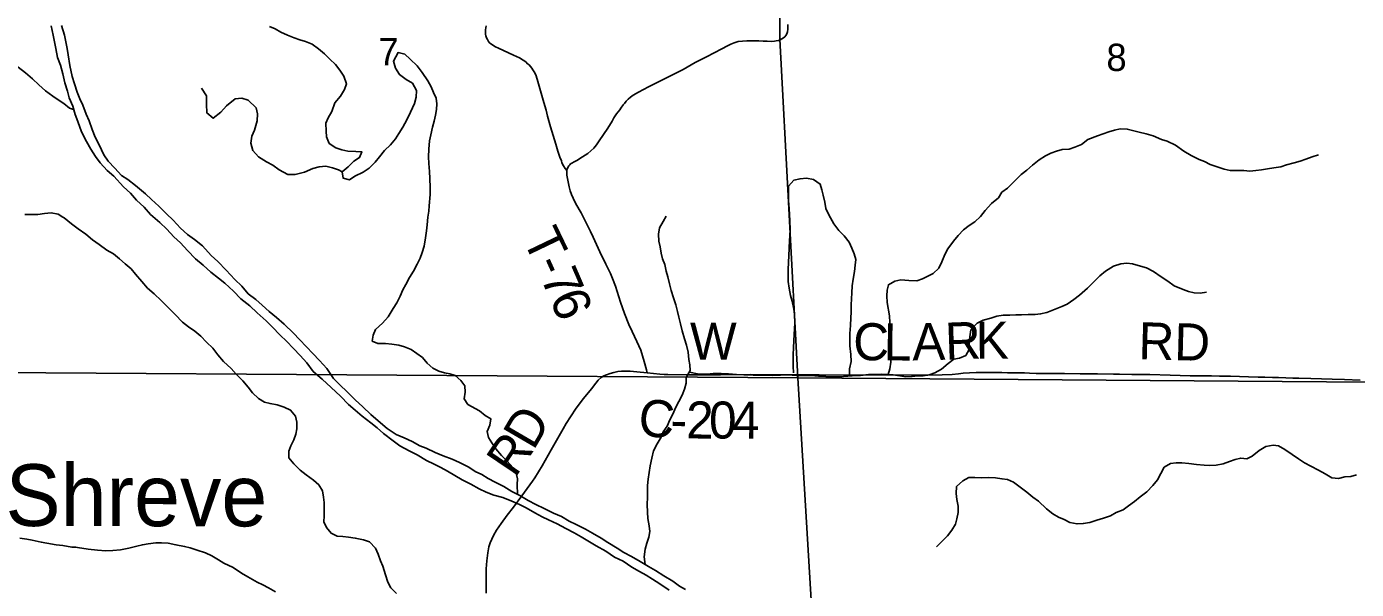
# Model space of a CAD drawing. Extents: x 1985906 to 2360102, y 891258 to 1222054.
# Drawn here: x 2108716 to 2119481, y 981202 to 985761 of the extents above; entities that cross this region are included whole.
import ezdxf

# ---------------------------------------------------------------- set-up
doc = ezdxf.new("R2010")
doc.units = 0
for name, color, linetype in [('GM_X_County_Road', 7, 'Continuous'), ('GM_X_County_Road_Text', 7, 'Continuous'), ('GM_X_Major_River', 7, 'Continuous'), ('GM_X_Minor_River', 7, 'Continuous'), ('GM_X_Minor_River_Text', 7, 'Continuous'), ('GM_X_Section', 7, 'Continuous'), ('GM_X_Section_Text', 7, 'Continuous'), ('GM_X_Township_Road', 7, 'Continuous'), ('GM_X_Township_Road_Text', 7, 'Continuous')]:
    doc.layers.add(name, color=color, linetype=linetype)

msp = doc.modelspace()

# ---------------------------------------------------------------- linework, layer by layer
at = {"layer": 'GM_X_County_Road'}
for points in [[(2112436, 981171), (2112435, 981319), (2112436, 981368), (2112441, 981434), (2112449, 981499), (2112459, 981548), (2112468, 981579), (2112481, 981610), (2112496, 981640), (2112521, 981682), (2112558, 981737), (2112607, 981803), (2112657, 981867), (2112726, 981959), (2112812, 982078), (2112831, 982105), (2112889, 982204), (2112962, 982332), (2113060, 982502), (2113085, 982545), (2113119, 982601), (2113165, 982669), (2113225, 982749), (2113289, 982827), (2113323, 982873), (2113344, 982898), (2113367, 982918), (2113390, 982932), (2113409, 982940), (2113440, 982950), (2113469, 982958), (2113501, 982966), (2113532, 982970), (2113562, 982971), (2113603, 982970), (2113655, 982965), (2113739, 982957)], [(2113739, 982957), (2113791, 982951), (2113842, 982945), (2113878, 982942), (2113907, 982942), (2114071, 982940), (2114332, 982941), (2114578, 982943), (2115117, 982940), (2115133, 982940), (2115880, 982938), (2116012, 982938), (2116127, 982940), (2116209, 982944), (2116260, 982949), (2116297, 982953), (2116349, 982955), (2116404, 982958), (2116448, 982959), (2116491, 982960), (2116541, 982960), (2116610, 982959), (2116656, 982957), (2116719, 982957), (2116793, 982955), (2116835, 982954), (2116889, 982952), (2116944, 982952), (2117021, 982952), (2117117, 982952), (2117245, 982949), (2117384, 982947), (2117515, 982945), (2117564, 982945), (2117662, 982944), (2117710, 982944), (2117760, 982944), (2117809, 982943), (2117973, 982937), (2118136, 982933), (2118218, 982932), (2118267, 982932), (2118307, 982931), (2118374, 982929), (2118462, 982929), (2118608, 982925), (2118686, 982922), (2118739, 982920), (2118801, 982919), (2118851, 982918), (2118909, 982916), (2118967, 982914), (2119015, 982912), (2119111, 982911), (2119285, 982906), (2119385, 982903), (2119511, 982898)]]:
    msp.add_lwpolyline(points, dxfattribs=at)
at = {"layer": 'GM_X_Major_River'}
for points in [[(2108914, 985766), (2108930, 985690), (2108942, 985636), (2108953, 985584), (2108967, 985511), (2108991, 985449), (2109009, 985379), (2109026, 985305), (2109046, 985237), (2109060, 985183), (2109089, 985115), (2109109, 985049), (2109131, 984991), (2109161, 984909), (2109202, 984829), (2109236, 984767), (2109274, 984709), (2109312, 984657), (2109369, 984596), (2109421, 984550), (2109501, 984462), (2109557, 984412), (2109606, 984356), (2109668, 984298), (2109720, 984239), (2109794, 984175), (2109850, 984121), (2109909, 984059), (2109961, 984009), (2110019, 983947), (2110083, 983880), (2110145, 983828), (2110206, 983772), (2110270, 983724), (2110320, 983682), (2110390, 983619), (2110450, 983557), (2110522, 983499), (2110581, 983443), (2110655, 983377)], [(2111437, 982680), (2111375, 982737), (2111313, 982799), (2111250, 982863), (2111200, 982911), (2111146, 982991), (2111086, 983057), (2111032, 983113), (2110981, 983166), (2110925, 983226), (2110877, 983278), (2110801, 983350), (2110739, 983404), (2110680, 983454), (2110622, 983505), (2110572, 983551), (2110510, 983597), (2110458, 983657), (2110402, 983713), (2110331, 983787), (2110265, 983858), (2110211, 983908), (2110139, 983984), (2110076, 984036), (2110018, 984076), (2109962, 984127), (2109902, 984193), (2109848, 984245), (2109786, 984307), (2109727, 984361), (2109677, 984405), (2109597, 984474), (2109535, 984522), (2109483, 984556), (2109429, 984614), (2109376, 984670), (2109340, 984722), (2109304, 984802), (2109272, 984864), (2109247, 984926), (2109221, 984998), (2109197, 985052), (2109170, 985124), (2109146, 985176), (2109126, 985230), (2109104, 985296), (2109085, 985356), (2109065, 985446), (2109053, 985532), (2109044, 985582), (2109034, 985636), (2109022, 985690), (2108998, 985770)], [(2110655, 983377), (2110705, 983329), (2110769, 983262), (2110819, 983212), (2110876, 983154), (2110930, 983098), (2110984, 983038), (2111036, 982966), (2111108, 982905), (2111181, 982837), (2111257, 982767), (2111323, 982701), (2111375, 982653), (2111433, 982605), (2111502, 982550), (2111554, 982510), (2111606, 982464), (2111682, 982406), (2111738, 982366), (2111814, 982325), (2111878, 982291), (2111952, 982247), (2112015, 982217), (2112069, 982190), (2112123, 982160), (2112183, 982124), (2112243, 982090), (2112311, 982055), (2112379, 982017), (2112435, 981989), (2112497, 981965), (2112571, 981946), (2112645, 981916), (2112705, 981890), (2112759, 981864), (2112831, 981821), (2112889, 981791), (2112941, 981765), (2113010, 981733), (2113082, 981696), (2113148, 981660), (2113204, 981628), (2113258, 981596), (2113326, 981556), (2113404, 981513), (2113476, 981463), (2113544, 981431), (2113616, 981383), (2113678, 981346), (2113731, 981318), (2113783, 981286), (2113841, 981246), (2113917, 981196)], [(2114051, 981201), (2114001, 981227), (2113946, 981269), (2113874, 981313), (2113808, 981354), (2113750, 981388), (2113684, 981428), (2113612, 981468), (2113550, 981501), (2113496, 981535), (2113422, 981583), (2113366, 981617), (2113297, 981658), (2113241, 981690), (2113165, 981728), (2113109, 981756), (2113045, 981792), (2112981, 981819), (2112905, 981857), (2112837, 981889), (2112775, 981922), (2112709, 981962), (2112645, 981996), (2112579, 982036), (2112509, 982072), (2112453, 982101), (2112400, 982133), (2112348, 982157), (2112296, 982191), (2112220, 982230), (2112162, 982256), (2112088, 982284), (2112022, 982310), (2111950, 982345), (2111900, 982365), (2111836, 982399), (2111772, 982429), (2111708, 982456), (2111636, 982506), (2111582, 982552), (2111503, 982620), (2111437, 982680)]]:
    msp.add_lwpolyline(points, dxfattribs=at)
at = {"layer": 'GM_X_Minor_River'}
for points in [[(2110681, 985762), (2110729, 985742), (2110773, 985716), (2110827, 985692), (2110883, 985670), (2110929, 985654), (2110973, 985640), (2111027, 985619), (2111079, 985581), (2111127, 985541), (2111171, 985497), (2111217, 985453), (2111251, 985408), (2111285, 985358), (2111305, 985296), (2111289, 985252), (2111256, 985196), (2111210, 985142), (2111186, 985073), (2111156, 985023), (2111138, 984979), (2111140, 984915), (2111144, 984867), (2111164, 984815), (2111220, 984780), (2111268, 984762), (2111316, 984752), (2111380, 984750), (2111430, 984746), (2111412, 984700), (2111364, 984670), (2111318, 984624), (2111270, 984584), (2111278, 984534), (2111330, 984519), (2111374, 984549), (2111440, 984581), (2111490, 984613), (2111538, 984662), (2111574, 984706), (2111614, 984756), (2111662, 984802), (2111702, 984852), (2111730, 984896), (2111762, 984946), (2111794, 985006), (2111824, 985068), (2111855, 985137), (2111869, 985189), (2111873, 985243), (2111839, 985303)], [(2109096, 985090), (2109062, 985099), (2109016, 985139), (2108972, 985167), (2108928, 985197), (2108868, 985240), (2108816, 985290), (2108764, 985338), (2108708, 985386), (2108648, 985431), (2108602, 985463), (2108540, 985501), (2108488, 985531), (2108446, 985542)], [(2111839, 985303), (2111789, 985331), (2111735, 985372), (2111703, 985424), (2111685, 985482), (2111723, 985550), (2111777, 985538), (2111821, 985498), (2111877, 985444), (2111919, 985389), (2111963, 985321), (2111991, 985273), (2112011, 985227), (2112031, 985182), (2112037, 985134), (2112033, 985088), (2112027, 985044), (2112016, 984994), (2112002, 984946), (2111988, 984884), (2111978, 984835), (2111972, 984769), (2111970, 984705), (2111972, 984651), (2111978, 984587), (2111980, 984530), (2111982, 984458), (2111982, 984402), (2111975, 984310), (2111971, 984266), (2111965, 984217), (2111959, 984155), (2111953, 984107), (2111945, 984049), (2111933, 983983), (2111919, 983931), (2111901, 983884), (2111877, 983836), (2111847, 983780), (2111815, 983728), (2111786, 983672), (2111762, 983628), (2111740, 983578), (2111712, 983522), (2111684, 983477), (2111642, 983409), (2111598, 983359), (2111540, 983307), (2111522, 983261), (2111514, 983213), (2111560, 983195), (2111620, 983193), (2111672, 983189), (2111728, 983180), (2111774, 983166), (2111828, 983144), (2111874, 983114), (2111920, 983080), (2111958, 983034), (2112004, 982995), (2112052, 982971), (2112098, 982957), (2112142, 982947), (2112186, 982935), (2112230, 982895), (2112264, 982851), (2112267, 982800), (2112259, 982746), (2112287, 982700), (2112383, 982648), (2112427, 982611), (2112473, 982585), (2112465, 982533), (2112445, 982481), (2112455, 982433), (2112483, 982389), (2112515, 982342), (2112561, 982288), (2112605, 982240), (2112653, 982190), (2112679, 982144), (2112691, 982099), (2112687, 982053), (2112691, 981972)], [(2111270, 984584), (2111242, 984600), (2111192, 984618), (2111138, 984630), (2111084, 984626), (2111032, 984612), (2110965, 984581), (2110891, 984563), (2110831, 984564), (2110761, 984600), (2110709, 984638), (2110657, 984666), (2110593, 984706), (2110548, 984757), (2110532, 984816), (2110538, 984872), (2110562, 984922), (2110583, 984998), (2110585, 985054), (2110573, 985104), (2110510, 985166), (2110457, 985180), (2110405, 985176), (2110333, 985119), (2110287, 985067), (2110226, 985018), (2110175, 985062), (2110171, 985132), (2110173, 985201), (2110133, 985262)], [(2115691, 982943), (2115703, 982989), (2115711, 983042), (2115709, 983090), (2115703, 983138), (2115699, 983194), (2115699, 983246), (2115703, 983363), (2115700, 983417), (2115682, 983525), (2115680, 983579), (2115682, 983626), (2115692, 983670), (2115744, 983700), (2115794, 983710), (2115858, 983704), (2115922, 983701), (2115968, 983719), (2116012, 983739), (2116056, 983761), (2116100, 983803), (2116126, 983856), (2116150, 983916), (2116174, 983960), (2116219, 984022), (2116257, 984070), (2116301, 984114), (2116345, 984150), (2116391, 984180), (2116439, 984222), (2116477, 984272), (2116527, 984328), (2116585, 984375), (2116611, 984419), (2116657, 984451), (2116768, 984563), (2116812, 984599), (2116858, 984639), (2116914, 984681), (2116964, 984713), (2117008, 984735), (2117052, 984753), (2117100, 984765), (2117156, 984767), (2117202, 984783), (2117256, 984805), (2117306, 984847), (2117384, 984875), (2117432, 984891), (2117478, 984909), (2117524, 984923), (2117570, 984933), (2117626, 984931), (2117678, 984917), (2117722, 984906), (2117780, 984892), (2117836, 984876), (2117902, 984846), (2117948, 984832), (2118016, 984800), (2118084, 984753), (2118144, 984717), (2118208, 984685), (2118252, 984667), (2118298, 984645), (2118410, 984606), (2118460, 984596), (2118522, 984596), (2118570, 984594), (2118618, 984590), (2118666, 984594), (2118714, 984600), (2118762, 984608), (2118812, 984616), (2118870, 984626), (2118914, 984640), (2118976, 984656), (2119027, 984672), (2119071, 984686), (2119123, 984706), (2119175, 984721)], [(2115378, 982930), (2115377, 982988), (2115391, 983048), (2115387, 983106), (2115379, 983175), (2115381, 983223), (2115381, 983275), (2115385, 983341), (2115389, 983401), (2115391, 983447), (2115392, 983506), (2115394, 983556), (2115396, 983604), (2115398, 983662), (2115406, 983714), (2115418, 983776), (2115424, 983829), (2115428, 983875), (2115414, 983919), (2115396, 983965), (2115374, 984015), (2115334, 984066), (2115290, 984110), (2115250, 984164), (2115209, 984236), (2115187, 984288), (2115177, 984339), (2115165, 984395), (2115153, 984439), (2115139, 984485), (2115087, 984521), (2115029, 984534), (2114977, 984528), (2114927, 984518), (2114885, 984468), (2114885, 984349), (2114889, 984287), (2114894, 984187), (2114898, 984116), (2114894, 984070), (2114892, 984026), (2114888, 983968), (2114886, 983902), (2114884, 983856), (2114880, 983789), (2114880, 983743), (2114882, 983697), (2114890, 983643), (2114901, 983583), (2114913, 983536), (2114927, 983472), (2114933, 983428), (2114935, 983360), (2114931, 983312), (2114927, 983219), (2114923, 983157), (2114921, 983107), (2114921, 983057), (2114921, 983011), (2114923, 982957)], [(2109010, 984218), (2108970, 984242), (2108916, 984252), (2108860, 984246), (2108808, 984239), (2108702, 984239)], [(2109468, 983880), (2109418, 983919), (2109366, 983951), (2109302, 983997), (2109250, 984033), (2109194, 984079), (2109132, 984122), (2109078, 984162), (2109020, 984212), (2109010, 984218)], [(2113723, 981405), (2113714, 981466), (2113724, 981528), (2113736, 981576), (2113754, 981624), (2113760, 981670), (2113756, 981716), (2113745, 981777), (2113741, 981827), (2113739, 981889), (2113741, 981949), (2113741, 981995), (2113743, 982044), (2113747, 982094), (2113755, 982148), (2113763, 982204), (2113777, 982266), (2113791, 982324), (2113821, 982382), (2113853, 982435), (2113870, 982479), (2113902, 982523), (2113924, 982575), (2113946, 982621), (2113972, 982677), (2113996, 982723), (2114022, 982775), (2114042, 982824), (2114056, 982872), (2114056, 982918), (2114088, 982974), (2114084, 983020), (2114076, 983064), (2114071, 983125), (2114059, 983181), (2114043, 983231), (2114023, 983297), (2114009, 983353), (2113997, 983408), (2113985, 983452), (2113971, 983508), (2113953, 983564), (2113935, 983622), (2113919, 983677), (2113907, 983733), (2113893, 983779), (2113883, 983833), (2113864, 983881), (2113854, 983925), (2113844, 983978), (2113834, 984022), (2113830, 984080), (2113840, 984130), (2113868, 984182), (2113894, 984226)], [(2111709, 981168), (2111665, 981216), (2111641, 981260), (2111621, 981321), (2111599, 981389), (2111581, 981433), (2111561, 981487), (2111541, 981537), (2111491, 981588), (2111443, 981604), (2111377, 981618), (2111323, 981626), (2111275, 981630), (2111229, 981634), (2111181, 981658), (2111143, 981703), (2111122, 981749), (2111124, 981797), (2111124, 981905), (2111120, 981949), (2111110, 982000), (2111082, 982048), (2111038, 982088), (2110980, 982130), (2110930, 982168), (2110880, 982219), (2110840, 982267), (2110840, 982321), (2110856, 982365), (2110878, 982413), (2110894, 982459), (2110903, 982504), (2110903, 982558), (2110893, 982604), (2110853, 982654), (2110801, 982678), (2110743, 982698), (2110687, 982707), (2110643, 982719), (2110593, 982749), (2110545, 982795), (2110509, 982839), (2110467, 982892), (2110413, 982946), (2110373, 982992), (2110311, 983048), (2110263, 983103), (2110223, 983157), (2110171, 983205), (2110127, 983253), (2110079, 983293), (2110027, 983328), (2109979, 983368), (2109919, 983430), (2109858, 983488), (2109804, 983541), (2109748, 983595), (2109694, 983643), (2109650, 983695), (2109598, 983756), (2109562, 983800), (2109514, 983840), (2109468, 983880)], [(2114081, 982963), (2114160, 982946), (2114224, 982946), (2114274, 982950), (2114338, 982952), (2114398, 982949), (2114462, 982943), (2114522, 982941), (2114598, 982937), (2114689, 982937), (2114753, 982935), (2114819, 982937), (2114881, 982939), (2114945, 982936), (2115007, 982936), (2115067, 982934), (2115127, 982930), (2115185, 982926), (2115253, 982924), (2115329, 982926), (2115399, 982932), (2115467, 982936), (2115531, 982942), (2115585, 982943), (2115635, 982945), (2115731, 982941), (2115785, 982931), (2115833, 982923), (2115885, 982927), (2115929, 982931), (2115975, 982933), (2116023, 982941), (2116069, 982957), (2116123, 982985), (2116175, 983033), (2116223, 983067), (2116269, 983075), (2116319, 983097), (2116347, 983145), (2116347, 983199), (2116352, 983249), (2116360, 983305), (2116410, 983358), (2116460, 983382), (2116522, 983399), (2116570, 983415), (2116622, 983423), (2116676, 983423), (2116724, 983425), (2116770, 983425), (2116824, 983429), (2116880, 983429), (2116924, 983433), (2116976, 983445), (2117096, 983493), (2117140, 983513), (2117194, 983549), (2117240, 983585), (2117304, 983641), (2117351, 983687), (2117403, 983741), (2117451, 983779), (2117515, 983819), (2117575, 983839), (2117623, 983845), (2117669, 983839), (2117733, 983821), (2117781, 983807), (2117839, 983777), (2117901, 983734), (2117955, 983700), (2118007, 983662), (2118079, 983630), (2118123, 983616), (2118169, 983603), (2118215, 983601), (2118267, 983611)], [(2116081, 981546), (2116121, 981588), (2116171, 981636), (2116207, 981682), (2116235, 981730), (2116247, 981775), (2116256, 981825), (2116256, 981875), (2116246, 981929), (2116240, 981979), (2116244, 982035), (2116296, 982082), (2116344, 982108), (2116392, 982109), (2116450, 982105), (2116504, 982109), (2116560, 982105), (2116612, 982099), (2116656, 982091), (2116704, 982071), (2116760, 982031), (2116812, 981990), (2116862, 981950), (2116908, 981916), (2116972, 981856), (2117024, 981814), (2117070, 981787), (2117114, 981767), (2117160, 981745), (2117220, 981733), (2117270, 981735), (2117322, 981745), (2117380, 981763), (2117434, 981779), (2117490, 981797), (2117536, 981825), (2117592, 981847), (2117636, 981879), (2117684, 981915), (2117730, 981953), (2117784, 981993), (2117832, 982045), (2117870, 982089), (2117899, 982141), (2117925, 982191), (2117977, 982223), (2118021, 982227), (2118067, 982227), (2118125, 982223), (2118187, 982213), (2118249, 982209), (2118295, 982207), (2118347, 982209), (2118403, 982219), (2118453, 982237), (2118501, 982255), (2118545, 982266), (2118593, 982260), (2118637, 982280), (2118695, 982328), (2118747, 982360), (2118807, 982370), (2118851, 982364), (2118901, 982334), (2118961, 982296), (2119013, 982260), (2119061, 982226), (2119111, 982199), (2119173, 982169), (2119227, 982137), (2119283, 982107), (2119335, 982101), (2119387, 982113), (2119435, 982117), (2119483, 982129)], [(2109114, 981543), (2109083, 981545), (2109009, 981558), (2108956, 981562), (2108880, 981576), (2108834, 981586), (2108762, 981600), (2108718, 981608), (2108660, 981616)], [(2110731, 981182), (2110675, 981214), (2110627, 981238), (2110583, 981262), (2110507, 981304), (2110455, 981334), (2110389, 981379), (2110313, 981415), (2110269, 981441), (2110215, 981473), (2110165, 981499), (2110097, 981520), (2110039, 981540), (2109995, 981550), (2109925, 981564), (2109861, 981576), (2109807, 981578), (2109761, 981580), (2109701, 981572), (2109653, 981564), (2109609, 981553), (2109543, 981537), (2109477, 981523), (2109415, 981517), (2109357, 981515), (2109289, 981521), (2109213, 981527), (2109129, 981541), (2109114, 981543)]]:
    msp.add_lwpolyline(points, dxfattribs=at)
at = {"layer": 'GM_X_Section'}
for points in [[(2114822, 988281), (2114814, 985660), (2114959, 982915), (2108465, 982960), (2108488, 988311)], [(2120191, 988188), (2120308, 982876), (2114959, 982915), (2114814, 985660), (2114822, 988281)], [(2114959, 982915), (2115107, 980441), (2115159, 977489), (2108525, 977560), (2108465, 982960)], [(2120308, 982876), (2120424, 977532), (2115159, 977489), (2115107, 980441), (2114959, 982915)]]:
    msp.add_lwpolyline(points, close=True, dxfattribs=at)
at = {"layer": 'GM_X_Township_Road'}
for points in [[(2113089, 984595), (2113076, 984612), (2113063, 984632), (2113050, 984658), (2113045, 984673), (2113033, 984703), (2113017, 984753), (2113000, 984809), (2112957, 984948), (2112933, 985036), (2112921, 985084), (2112904, 985147), (2112848, 985334), (2112837, 985369), (2112824, 985395), (2112815, 985410), (2112805, 985425), (2112794, 985438), (2112784, 985450), (2112772, 985460), (2112757, 985474), (2112735, 985489), (2112705, 985507), (2112658, 985528), (2112535, 985585), (2112511, 985598), (2112482, 985616), (2112464, 985629), (2112454, 985641), (2112446, 985655), (2112440, 985669), (2112434, 985685), (2112430, 985700), (2112430, 985716), (2112430, 985734), (2112435, 985766)], [(2113089, 984595), (2113091, 984607), (2113096, 984619), (2113105, 984633), (2113114, 984642), (2113120, 984648), (2113130, 984655), (2113148, 984665), (2113169, 984677), (2113217, 984707), (2113258, 984734), (2113284, 984755), (2113307, 984777), (2113329, 984802), (2113352, 984835), (2113387, 984887), (2113420, 984938), (2113455, 984994), (2113471, 985022), (2113492, 985054), (2113517, 985087), (2113526, 985101), (2113545, 985127), (2113556, 985139), (2113569, 985156), (2113585, 985173), (2113604, 985189), (2113626, 985205), (2113669, 985230), (2113749, 985273), (2113865, 985330), (2113944, 985370), (2114030, 985414), (2114129, 985469), (2114221, 985516), (2114345, 985580), (2114389, 985605), (2114417, 985619), (2114444, 985630), (2114476, 985639), (2114511, 985644), (2114546, 985646), (2114593, 985646), (2114644, 985645), (2114678, 985644), (2114711, 985643), (2114744, 985641), (2114770, 985643), (2114785, 985646), (2114803, 985649), (2114817, 985654), (2114831, 985662), (2114843, 985669), (2114853, 985678), (2114863, 985688), (2114871, 985703), (2114875, 985717), (2114877, 985739), (2114877, 985777)], [(2113739, 982957), (2113734, 982980), (2113715, 983049), (2113687, 983139), (2113655, 983210), (2113619, 983292), (2113591, 983349), (2113556, 983438), (2113523, 983528), (2113483, 983658), (2113459, 983721), (2113442, 983762), (2113405, 983837), (2113357, 983936), (2113344, 983966), (2113303, 984054), (2113280, 984101), (2113242, 984178), (2113204, 984252), (2113163, 984326), (2113140, 984370), (2113127, 984400), (2113117, 984431), (2113108, 984462), (2113089, 984558), (2113088, 984575), (2113088, 984591), (2113089, 984595)]]:
    msp.add_lwpolyline(points, dxfattribs=at)

# ---------------------------------------------------------------- texts
at = {"layer": 'GM_X_County_Road_Text'}
for s, rotation, p in [('W', 0, (2114086, 983063)), ('C', 359.5824, (2115407, 983059)), ('L', 359.6913, (2115654, 983057)), ('A', 1.3032, (2115888, 983056)), ('R', 2.0668, (2116156, 983062)), ('K', 0.2532, (2116400, 983071)), ('RD', 358.5218, (2117714, 983067)), ('D', 59.7292, (2112819, 982321)), ('C', 355.3934, (2113661, 982448)), ('2', 359.6347, (2114054, 982425)), ('0', 359.9159, (2114240, 982424)), ('4', 359.9957, (2114426, 982424)), ('-', 359.0334, (2113927, 982427)), ('R', 56.016, (2112670, 982099))]:
    msp.add_text(s, height=300, rotation=rotation, dxfattribs=at).set_placement(p)
at = {"layer": 'GM_X_Minor_River_Text'}
msp.add_text('Shreve', height=500.1, rotation=359.9084, dxfattribs=at).set_placement((2108545, 981716))
at = {"layer": 'GM_X_Section_Text'}
for s, p in [('7', (2111563, 985447)), ('8', (2117457, 985401))]:
    msp.add_text(s, height=221, rotation=0, dxfattribs=at).set_placement(p)
at = {"layer": 'GM_X_Township_Road_Text'}
for s, rotation, p in [('T', 295.6412, (2112727, 984042)), ('-', 294.2831, (2112823, 983841)), ('7', 293.3144, (2112873, 983730)), ('6', 292.5228, (2112946, 983562))]:
    msp.add_text(s, height=300, rotation=rotation, dxfattribs=at).set_placement(p)

doc.saveas('drawing.dxf')
